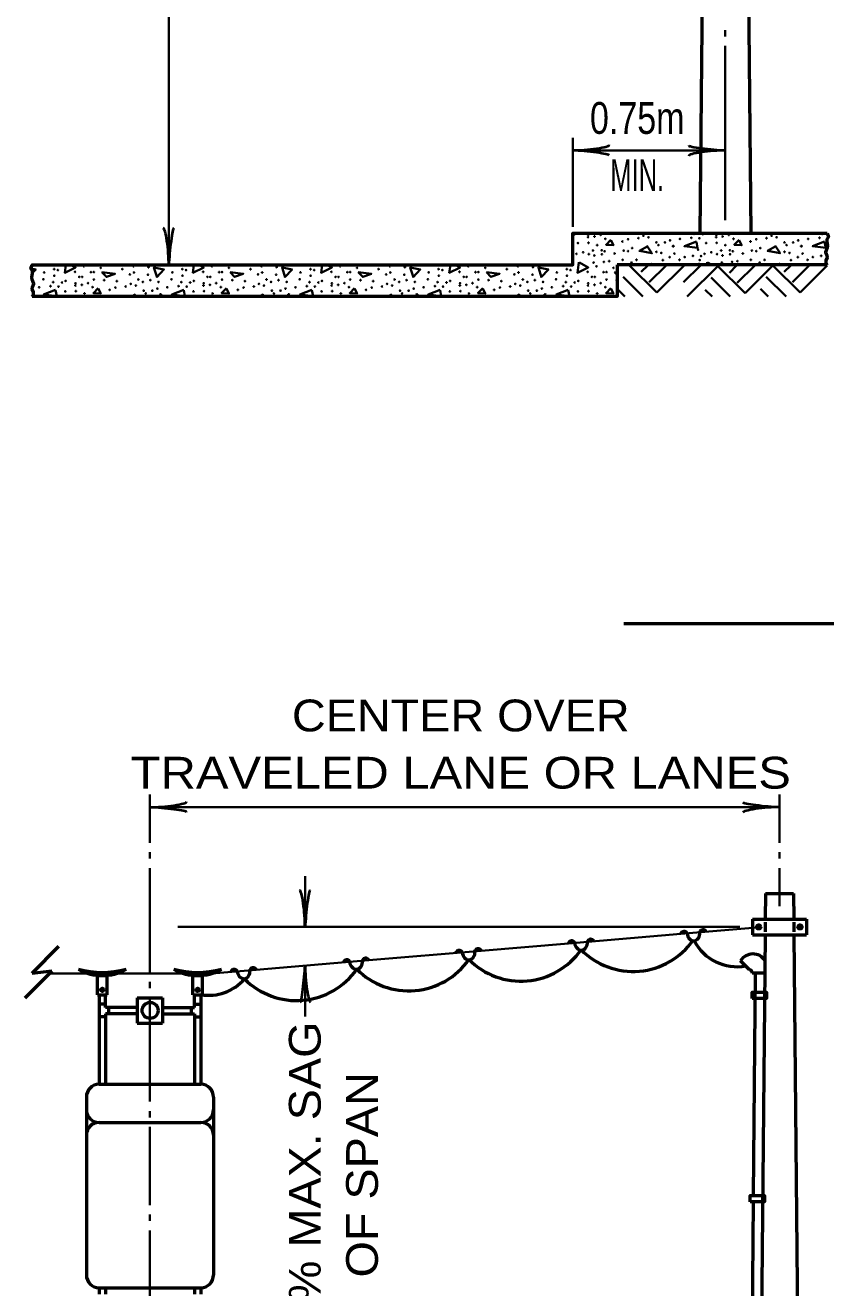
# Model space of a CAD drawing. Extents: x -35 to 821, y -10 to 534.
# Drawn here: x 369.7 to 446, y 205.9 to 325 of the extents above; entities that cross this region are included whole.
import ezdxf
from ezdxf.enums import TextEntityAlignment as Align

# ---------------------------------------------------------------- set-up
doc = ezdxf.new("R2010")
doc.units = 0
doc.header["$LTSCALE"] = 1.2
doc.layers.add('1', color=7, linetype='Continuous', lineweight=35)

msp = doc.modelspace()

# ---------------------------------------------------------------- hatches: boundary and pattern name
at = {"layer": '1'}
for points in [[(439.118, 239.937, 1), (438.73, 239.937, 1)], [(443.008, 239.937, 1), (442.62, 239.937, 1)], [(377.117, 233.997, 1), (376.817, 233.997, 1)], [(386.119, 233.993, 1), (385.819, 233.993, 1)]]:
    msp.add_hatch(color=256, dxfattribs=at).paths.add_polyline_path(points)

# ---------------------------------------------------------------- linework, layer by layer
at = {"layer": '1', "lineweight": 53}
for p, q in [((434.268, 402.619), (433.368, 305.418)), ((437.268, 402.619), (438.168, 305.418)), ((445.368, 302.418), (425.567, 302.418)), ((446.005, 268.555), (426.205, 268.555)), ((439.564, 243.084), (439.542, 240.684)), ((439.564, 243.084), (442.209, 243.084)), ((442.209, 243.084), (442.231, 240.684)), ((438.342, 240.684), (443.431, 240.684)), ((438.342, 240.684), (438.342, 239.184)), ((443.431, 240.684), (443.431, 239.184)), ((439.539, 240.384), (439.531, 239.484)), ((442.234, 240.384), (442.242, 239.484)), ((438.342, 239.184), (443.431, 239.184)), ((439.528, 239.184), (438.487, 126.685)), ((442.245, 239.184), (443.287, 126.685)), ((370.341, 235.562), (372.886, 238.108)), ((438.067, 235.894), (437.219, 236.743)), ((369.701, 233.251), (372.247, 235.797)), ((370.341, 235.562), (372.247, 235.797)), ((376.52, 233.542), (376.52, 235.342)), ((377.42, 233.542), (377.42, 235.342)), ((385.52, 233.542), (385.52, 235.342)), ((386.42, 233.542), (386.42, 235.342)), ((439.495, 235.584), (438.295, 235.584)), ((438.595, 235.584), (438.4, 214.593)), ((376.52, 233.542), (377.42, 233.542)), ((376.67, 233.542), (376.67, 225.085)), ((377.27, 232.342), (377.27, 233.542)), ((385.52, 233.542), (386.42, 233.542)), ((385.67, 232.342), (385.67, 233.542)), ((386.27, 233.542), (386.27, 225.085)), ((377.27, 232.642), (376.67, 232.642)), ((380.27, 232.342), (377.27, 232.342)), ((377.57, 232.342), (377.57, 231.742)), ((380.27, 233.242), (382.67, 233.242)), ((380.27, 233.242), (380.27, 230.842)), ((382.67, 233.242), (382.67, 230.842)), ((382.67, 232.342), (385.67, 232.342)), ((385.37, 232.342), (385.37, 231.742)), ((385.67, 232.642), (386.27, 232.642)), ((377.27, 231.442), (376.67, 231.442)), ((380.27, 231.742), (377.27, 231.742)), ((377.27, 231.742), (377.27, 225.085)), ((382.67, 231.742), (385.67, 231.742)), ((385.67, 231.742), (385.67, 225.085)), ((385.67, 231.442), (386.27, 231.442)), ((380.27, 230.842), (382.67, 230.842)), ((376.67, 225.085), (386.27, 225.085)), ((375.47, 223.885), (375.47, 207.085)), ((387.47, 223.885), (387.47, 207.085)), ((376.67, 221.485), (386.27, 221.485)), ((438.395, 213.985), (437.884, 158.795)), ((376.67, 205.885), (386.27, 205.885)), ((376.67, 205.885), (376.67, 205.285)), ((377.27, 205.885), (377.27, 205.285)), ((385.67, 205.885), (385.67, 205.285)), ((386.27, 205.885), (386.27, 205.285))]:
    msp.add_line(p, q, dxfattribs=at)
at = {"layer": '1'}
for p, q in [((383.251, 393.619), (383.251, 302.418)), ((435.768, 323.979), (435.768, 324.579)), ((435.768, 323.079), (435.768, 306.619)), ((421.368, 306.019), (421.368, 314.418)), ((421.368, 313.219), (435.768, 313.219)), ((434.012, 302.418), (434.049, 302.678)), ((434.097, 302.654), (434.509, 302.418)), ((425.313, 301.718), (425.567, 301.689)), ((425.567, 301.463), (425.313, 301.718)), ((426.744, 302.37), (429.312, 299.803)), ((428.448, 302.37), (427.824, 301.747)), ((430.175, 302.37), (428.591, 300.786)), ((431.88, 302.37), (429.312, 299.803)), ((433.416, 302.37), (431.832, 300.786)), ((435.12, 302.37), (432.168, 299.418)), ((435, 302.37), (437.639, 299.731)), ((436.824, 302.37), (436.151, 301.675)), ((438.552, 302.37), (436.896, 300.714)), ((440.256, 302.37), (437.639, 299.731)), ((440.256, 302.37), (442.824, 299.803)), ((441.96, 302.37), (441.336, 301.747)), ((443.688, 302.37), (442.103, 300.786)), ((445.392, 302.37), (442.824, 299.803)), ((426.12, 301.291), (427.992, 299.418)), ((434.424, 301.219), (436.243, 299.418)), ((439.632, 301.291), (441.504, 299.418)), ((380.073, 299.606), (379.729, 299.418)), ((380.161, 299.418), (380.025, 299.63)), ((392.169, 299.606), (391.825, 299.418)), ((392.257, 299.418), (392.121, 299.63)), ((404.265, 299.606), (403.921, 299.418)), ((404.353, 299.418), (404.217, 299.63)), ((416.361, 299.606), (416.017, 299.418)), ((416.449, 299.418), (416.313, 299.63)), ((425.567, 300.139), (426.288, 299.418)), ((433.872, 300.067), (434.519, 299.418)), ((439.079, 300.139), (439.8, 299.418)), ((381.47, 252.442), (381.47, 247.884)), ((440.887, 247.884), (440.887, 252.442)), ((381.47, 251.242), (440.887, 251.242)), ((381.47, 246.984), (381.47, 246.384)), ((440.887, 246.384), (440.887, 246.984)), ((381.47, 245.484), (381.47, 235.642)), ((440.887, 241.884), (440.887, 245.484)), ((396.113, 239.934), (396.113, 244.734)), ((384.113, 239.934), (437.142, 239.934)), ((431.575, 239.278), (438.738, 239.882)), ((412.739, 237.69), (420.961, 238.384)), ((420.958, 238.383), (431.575, 239.278)), ((402.12, 236.796), (412.739, 237.691)), ((391.505, 235.901), (402.12, 236.796)), ((396.113, 231.489), (396.113, 236.289)), ((375.622, 235.548), (371.998, 235.548)), ((384.622, 235.548), (378.318, 235.548)), ((381.47, 234.742), (381.47, 234.142)), ((387.317, 235.548), (391.505, 235.901)), ((381.47, 229.642), (381.47, 223.464)), ((381.47, 222.564), (381.47, 221.964)), ((381.47, 221.064), (381.47, 214.885)), ((381.47, 214.885), (381.47, 213.685)), ((381.47, 212.785), (381.47, 212.185)), ((381.47, 211.285), (381.47, 197.779))]:
    msp.add_line(p, q, dxfattribs=at)
at = {"layer": '1', "lineweight": 53}
for points in [[(370.368, 299.418), (370.477, 299.576), (370.483, 299.832), (370.352, 300.126), (370.372, 300.296), (370.509, 300.623), (370.359, 301.036), (370.326, 301.225), (370.392, 301.631), (370.372, 301.821), (370.235, 302.076), (370.368, 302.418), (421.368, 302.418), (421.368, 305.418), (445.368, 305.418)], [(445.368, 305.418), (445.501, 305.076), (445.363, 304.821), (445.344, 304.631), (445.409, 304.225), (445.376, 304.036), (445.226, 303.623), (445.363, 303.296), (445.383, 303.126), (445.252, 302.832), (445.258, 302.576), (445.368, 302.418)], [(425.567, 302.418), (425.567, 299.418), (370.368, 299.418)]]:
    msp.add_lwpolyline(points, dxfattribs=at)
at = {"layer": '1'}
for points in [[(424.977, 304.79), (424.521, 304.31), (425.217, 304.262), (424.977, 304.742)], [(428.457, 304.166), (427.665, 303.734), (428.841, 303.518), (428.409, 304.19)], [(433.041, 304.622), (431.913, 304.166), (433.161, 304.022), (433.041, 304.574)], [(437.073, 304.79), (436.617, 304.31), (437.313, 304.262), (437.073, 304.742)], [(440.553, 304.166), (439.761, 303.734), (440.937, 303.518), (440.505, 304.19)], [(445.137, 304.622), (444.009, 304.166), (445.257, 304.022), (445.137, 304.574)], [(422.001, 302.654), (422.841, 302.174), (421.809, 301.67), (421.953, 302.678)], [(370.235, 302.075), (370.689, 301.982), (370.389, 301.66)], [(374.029, 302.418), (374.457, 302.174), (373.425, 301.67), (373.531, 302.418)], [(382.137, 301.214), (381.849, 302.174), (382.785, 301.982), (382.113, 301.262)], [(386.125, 302.418), (386.553, 302.174), (385.521, 301.67), (385.627, 302.418)], [(394.233, 301.214), (393.945, 302.174), (394.881, 301.982), (394.209, 301.262)], [(398.221, 302.418), (398.649, 302.174), (397.617, 301.67), (397.724, 302.418)], [(406.329, 301.214), (406.041, 302.174), (406.977, 301.982), (406.305, 301.262)], [(410.317, 302.418), (410.745, 302.174), (409.713, 301.67), (409.82, 302.418)], [(418.425, 301.214), (418.137, 302.174), (419.073, 301.982), (418.401, 301.262)], [(372.561, 300.062), (371.433, 299.606), (372.681, 299.462), (372.561, 300.014)], [(376.593, 300.23), (376.137, 299.75), (376.833, 299.702), (376.593, 300.182)], [(384.657, 300.062), (383.529, 299.606), (384.777, 299.462), (384.657, 300.014)], [(388.689, 300.23), (388.233, 299.75), (388.929, 299.702), (388.689, 300.182)], [(396.753, 300.062), (395.625, 299.606), (396.873, 299.462), (396.753, 300.014)], [(400.785, 300.23), (400.329, 299.75), (401.025, 299.702), (400.785, 300.182)], [(408.849, 300.062), (407.721, 299.606), (408.969, 299.462), (408.849, 300.014)], [(412.881, 300.23), (412.425, 299.75), (413.121, 299.702), (412.881, 300.182)], [(420.945, 300.062), (419.817, 299.606), (421.065, 299.462), (420.945, 300.014)], [(424.977, 300.23), (424.521, 299.75), (425.217, 299.702), (424.977, 300.182)], [(381.47, 233.242), (381.47, 230.242), (381.47, 229.642)]]:
    msp.add_lwpolyline(points, dxfattribs=at)
for points in [[(376.929, 301.718), (378.177, 301.574), (377.361, 301.286)], [(389.025, 301.718), (390.273, 301.574), (389.457, 301.286)], [(401.121, 301.718), (402.369, 301.574), (401.553, 301.286)], [(413.217, 301.718), (414.465, 301.574), (413.649, 301.286)]]:
    msp.add_lwpolyline(points, close=True, dxfattribs=at)
at = {"layer": '1', "lineweight": 53}
for points in [[(438.295, 233.184), (438.295, 233.784), (439.645, 233.784), (439.645, 233.184)], [(438.123, 213.993), (438.123, 214.593), (439.473, 214.593), (439.473, 213.993)]]:
    msp.add_lwpolyline(points, close=True, dxfattribs=at)
at = {"layer": '1'}
for centre in [(421.56, 305.314), (422.816, 305.034), (422.832, 305.235), (423.42, 305.097), (424.009, 305.251), (428.042, 305.171), (428.519, 305.018), (429.187, 305.362), (430.666, 305.362), (432.813, 305.346), (433.656, 305.314), (434.912, 305.034), (434.928, 305.235), (435.516, 305.097), (436.105, 305.251), (440.138, 305.171), (440.615, 305.018), (441.283, 305.362), (442.762, 305.362), (444.909, 305.346), (421.862, 304.477), (422.864, 304.493), (423.675, 304.27), (424.104, 303.793), (424.447, 304.875), (426.054, 304.62), (426.594, 304.827), (426.976, 304), (427.564, 304.938), (429.266, 304.541), (429.457, 304.286), (430.077, 304.541), (430.554, 304.731), (430.825, 304.175), (430.888, 304.175), (431.493, 304.859), (432.558, 304.97), (433.194, 303.856), (433.322, 304.922), (433.958, 304.477), (434.96, 304.493), (435.771, 304.27), (436.2, 303.793), (436.543, 304.875), (438.15, 304.62), (438.69, 304.827), (439.072, 304), (439.66, 304.938), (441.362, 304.541), (441.553, 304.286), (442.173, 304.541), (442.65, 304.731), (442.921, 304.175), (442.984, 304.175), (443.589, 304.859), (444.654, 304.97), (421.719, 303.459), (422.355, 303.602), (422.896, 303.427), (423.277, 303.777), (423.341, 302.631), (423.404, 303.3), (424.12, 303.411), (424.311, 302.695), (424.384, 303.697), (424.813, 302.759), (425.322, 303.49), (426.085, 302.886), (426.181, 303.761), (426.594, 303.713), (426.912, 302.631), (427.389, 302.886), (429.266, 303.65), (429.727, 303.538), (429.87, 302.854), (430.523, 303.141), (430.968, 303.475), (431.445, 302.886), (431.938, 303.156), (432.717, 303.268), (433.353, 302.87), (433.481, 303.252), (433.815, 303.459), (434.451, 303.602), (434.992, 303.427), (435.373, 303.777), (435.437, 302.631), (435.5, 303.3), (436.216, 303.411), (436.407, 302.695), (436.48, 303.697), (436.909, 302.759), (437.418, 303.49), (438.181, 302.886), (438.277, 303.761), (438.69, 303.713), (439.008, 302.631), (439.485, 302.886), (441.362, 303.65), (441.823, 303.538), (441.966, 302.854), (442.619, 303.141), (443.064, 303.475), (443.541, 302.886), (444.034, 303.156), (444.813, 303.268), (371.49, 301.709), (372.428, 302.011), (372.778, 301.931), (374.4, 301.756), (375.227, 302.281), (375.903, 301.722), (376.175, 301.741), (376.827, 302.138), (378.862, 302.011), (379.578, 301.518), (379.912, 302.281), (379.96, 301.693), (381.28, 301.486), (381.327, 302.202), (383.586, 301.709), (384.524, 302.011), (384.874, 301.931), (386.496, 301.756), (387.323, 302.281), (387.999, 301.722), (388.271, 301.741), (388.923, 302.138), (390.958, 302.011), (391.674, 301.518), (392.008, 302.281), (392.056, 301.693), (393.376, 301.486), (393.423, 302.202), (395.682, 301.709), (396.62, 302.011), (396.97, 301.931), (398.592, 301.756), (399.419, 302.281), (400.095, 301.722), (400.367, 301.741), (401.019, 302.138), (403.054, 302.011), (403.77, 301.518), (404.104, 302.281), (404.152, 301.693), (405.472, 301.486), (405.519, 302.202), (407.778, 301.709), (408.716, 302.011), (409.066, 301.931), (410.688, 301.756), (411.515, 302.281), (412.191, 301.722), (412.463, 301.741), (413.115, 302.138), (415.15, 302.011), (415.866, 301.518), (416.2, 302.281), (416.248, 301.693), (417.568, 301.486), (417.615, 302.202), (419.874, 301.709), (420.812, 302.011), (421.162, 301.931), (422.784, 301.756), (423.611, 302.281), (424.287, 301.722), (424.559, 301.741), (425.211, 302.138), (428.789, 302.488), (433.274, 302.504), (440.885, 302.488), (371.013, 300.299), (371.41, 301.056), (372.078, 300.41), (372.333, 300.786), (372.444, 301.391), (372.842, 300.362), (373.176, 300.754), (373.51, 300.897), (374.432, 300.474), (374.448, 300.675), (374.798, 301.279), (375.036, 300.537), (375.068, 301.279), (375.625, 300.691), (376.063, 300.315), (376.175, 301.025), (377.145, 300.977), (378.21, 300.267), (378.338, 300.881), (379.18, 300.378), (379.658, 300.611), (380.135, 300.458), (380.373, 301.041), (380.803, 300.802), (381.502, 300.977), (382.282, 300.802), (383.109, 300.299), (383.506, 301.056), (384.174, 300.41), (384.429, 300.786), (384.54, 301.391), (384.938, 300.362), (385.272, 300.754), (385.606, 300.897), (386.528, 300.474), (386.544, 300.675), (386.894, 301.279), (387.132, 300.537), (387.164, 301.279), (387.721, 300.691), (388.159, 300.315), (388.271, 301.025), (389.241, 300.977), (390.306, 300.267), (390.434, 300.881), (391.276, 300.378), (391.754, 300.611), (392.231, 300.458), (392.469, 301.041), (392.899, 300.802), (393.598, 300.977), (394.378, 300.802), (395.205, 300.299), (395.602, 301.056), (396.27, 300.41), (396.525, 300.786), (396.636, 301.391), (397.034, 300.362), (397.368, 300.754), (397.702, 300.897), (398.624, 300.474), (398.64, 300.675), (398.99, 301.279), (399.228, 300.537), (399.26, 301.279), (399.817, 300.691), (400.255, 300.315), (400.367, 301.025), (401.337, 300.977), (402.402, 300.267), (402.53, 300.881), (403.372, 300.378), (403.85, 300.611), (404.327, 300.458), (404.565, 301.041), (404.995, 300.802), (405.694, 300.977), (406.474, 300.802), (407.301, 300.299), (407.698, 301.056), (408.366, 300.41), (408.621, 300.786), (408.732, 301.391), (409.13, 300.362), (409.464, 300.754), (409.798, 300.897), (410.72, 300.474), (410.736, 300.675), (411.086, 301.279), (411.324, 300.537), (411.356, 301.279), (411.913, 300.691), (412.351, 300.315), (412.463, 301.025), (413.433, 300.977), (414.498, 300.267), (414.626, 300.881), (415.468, 300.378), (415.946, 300.611), (416.423, 300.458), (416.661, 301.041), (417.091, 300.802), (417.79, 300.977), (418.57, 300.802), (419.397, 300.299), (419.794, 301.056), (420.462, 300.41), (420.717, 300.786), (420.828, 301.391), (421.226, 300.362), (421.56, 300.754), (421.894, 300.897), (422.816, 300.474), (422.832, 300.675), (423.182, 301.279), (423.42, 300.537), (423.452, 301.279), (424.009, 300.691), (424.447, 300.315), (424.559, 301.025), (425.529, 300.977), (373.478, 299.917), (374.48, 299.933), (375.291, 299.71), (377.67, 300.06), (380.882, 299.981), (381.073, 299.726), (381.693, 299.981), (382.17, 300.171), (382.441, 299.615), (382.504, 299.615), (385.574, 299.917), (386.576, 299.933), (387.387, 299.71), (389.766, 300.06), (392.978, 299.981), (393.169, 299.726), (393.789, 299.981), (394.266, 300.171), (394.537, 299.615), (394.6, 299.615), (397.67, 299.917), (398.672, 299.933), (399.483, 299.71), (401.862, 300.06), (405.074, 299.981), (405.265, 299.726), (405.885, 299.981), (406.362, 300.171), (406.633, 299.615), (406.696, 299.615), (409.766, 299.917), (410.768, 299.933), (411.579, 299.71), (413.958, 300.06), (417.17, 299.981), (417.361, 299.726), (417.981, 299.981), (418.458, 300.171), (418.729, 299.615), (418.792, 299.615), (421.862, 299.917), (422.864, 299.933), (423.675, 299.71)]:
    msp.add_circle(centre, 0.0318, dxfattribs=at)
at = {"layer": '1', "lineweight": 53}
for centre, radius in [((438.924, 239.937), 0.194), ((442.814, 239.937), 0.194), ((376.967, 233.997), 0.15), ((385.969, 233.993), 0.15), ((381.484, 232.055), 0.75)]:
    msp.add_circle(centre, radius, dxfattribs=at)
at = {"layer": '1'}
for centre, start, end in [((426.722, 305.441), 226.35082, 313.64918), ((438.818, 305.441), 226.35082, 313.64918), ((445.29, 303.856), 32.83014, 287.06312), ((445.418, 304.922), 61.61934, 241.7845), ((421.385, 303.252), 237.37076, 122.62924), ((371.299, 302.441), 223.9797, 316.0203), ((371.919, 302.409), 162.01481, 17.98519), ((377.638, 302.409), 162.01481, 17.98519), ((383.395, 302.441), 223.9797, 316.0203), ((384.015, 302.409), 162.01481, 17.98519), ((389.734, 302.409), 162.01481, 17.98519), ((395.491, 302.441), 223.9797, 316.0203), ((396.111, 302.409), 162.01481, 17.98519), ((401.83, 302.409), 162.01481, 17.98519), ((407.587, 302.441), 223.9797, 316.0203), ((408.207, 302.409), 162.01481, 17.98519), ((413.926, 302.409), 162.01481, 17.98519), ((419.683, 302.441), 223.9797, 316.0203), ((420.303, 302.409), 162.01481, 17.98519), ((426.022, 302.409), 17.98519, 162.01481), ((431.779, 302.441), 316.0203, 223.9797), ((432.399, 302.409), 17.98519, 162.01481), ((438.118, 302.409), 17.98519, 162.01481), ((443.875, 302.441), 316.0203, 223.9797), ((444.495, 302.409), 17.98519, 162.01481), ((378.592, 299.44), 318.30023, 221.69977), ((390.688, 299.44), 318.30023, 221.69977), ((402.784, 299.44), 318.30023, 221.69977), ((414.88, 299.44), 318.30023, 221.69977)]:
    msp.add_arc(centre, 0.0318, start, end, dxfattribs=at)
at = {"layer": '1', "lineweight": 53}
for centre, radius, start, end in [((431.883, 239.192), 0.32, 25.5313, 164.45861), ((433.676, 239.349), 0.32, 24.08975, 164.4687), ((421.267, 238.297), 0.32, 25.5313, 164.45861), ((427.062, 242.653), 6.917, 224.78783, 325.11132), ((423.06, 238.454), 0.32, 24.08975, 164.4687), ((436.868, 240.732), 4.547, 207.50003, 280.53329), ((410.653, 237.403), 0.32, 25.5313, 164.45861), ((416.479, 241.736), 6.917, 224.78783, 325.11132), ((412.446, 237.56), 0.32, 24.08975, 164.4687), ((438.374, 236.03), 1.357, 32.91213, 148.34152), ((376.97, 244.23), 8.588, 254.81071, 285.18929), ((376.97, 239.861), 4.519, 240.13717, 299.86284), ((385.97, 244.23), 8.588, 254.81071, 285.18929), ((385.97, 239.861), 4.519, 240.13717, 299.86284), ((389.42, 235.613), 0.32, 25.5313, 164.45861), ((395.314, 239.903), 6.917, 224.78783, 325.11132), ((391.213, 235.77), 0.32, 24.08975, 164.4687), ((400.035, 236.508), 0.32, 25.5313, 164.45861), ((405.897, 240.82), 6.917, 224.78783, 325.11132), ((401.828, 236.665), 0.32, 24.08975, 164.4687), ((387.002, 237.997), 4.514, 260.66909, 318.91993), ((438.057, 235.648), 0.246, 344.97633, 87.57779), ((376.67, 223.885), 1.2, 90, 180), ((386.27, 223.885), 1.2, 0, 90), ((376.67, 222.685), 1.2, 180, 270), ((386.27, 222.685), 1.2, 270, 0), ((376.67, 220.285), 1.2, 90, 180), ((386.27, 220.285), 1.2, 0, 90), ((376.67, 207.085), 1.2, 180, 270), ((386.27, 207.085), 1.2, 270, 0)]:
    msp.add_arc(centre, radius, start, end, dxfattribs=at)
at = {"layer": '1', "lineweight": 40}
for centre, major_axis, ratio, start_param, end_param in [((422.677, 313.55), (-2.143, -0.187), 0.122415, 0.8963533, 3.1415927), ((422.677, 313.55), (-2.143, -0.187), 0.122415, 0.8963533, 3.1415927), ((434.423, 313.472), (2.108, -0.211), 0.07063, 3.1407148, 5.41811), ((422.712, 312.965), (-2.108, 0.211), 0.07063, 3.1407148, 5.41811), ((422.712, 312.965), (-2.108, 0.211), 0.07063, 3.1407148, 5.41811), ((434.458, 312.887), (2.143, 0.187), 0.122415, 0.8963533, 3.1415927), ((382.919, 303.728), (0.187, -2.143), 0.122415, 0.8963533, 3.1415927), ((383.505, 303.763), (-0.211, -2.108), 0.07063, 3.1407148, 5.41811), ((382.79, 251.564), (-2.143, -0.187), 0.122415, 0.8963533, 3.1415927), ((439.542, 251.496), (2.108, -0.211), 0.07063, 3.1407148, 5.41811), ((382.825, 250.979), (-2.108, 0.211), 0.07063, 3.1407148, 5.41811), ((439.577, 250.911), (2.143, 0.187), 0.122415, 0.8963533, 3.1415927), ((395.782, 241.243), (0.187, -2.143), 0.122415, 0.8963533, 3.1415927), ((395.782, 241.243), (0.187, -2.143), 0.122415, 0.8963533, 3.1415927), ((396.367, 241.278), (-0.211, -2.108), 0.07063, 3.1407148, 5.41811), ((396.367, 241.278), (-0.211, -2.108), 0.07063, 3.1407148, 5.41811), ((395.859, 234.945), (0.211, 2.108), 0.07063, 3.1407148, 5.41811), ((395.859, 234.945), (0.211, 2.108), 0.07063, 3.1407148, 5.41811), ((396.445, 234.98), (-0.187, 2.143), 0.122415, 0.8963533, 3.1415927), ((396.445, 234.98), (-0.187, 2.143), 0.122415, 0.8963533, 3.1415927)]:
    msp.add_ellipse(centre, major_axis=major_axis, ratio=ratio, start_param=start_param, end_param=end_param, dxfattribs=at)
at = {"layer": '1', "lineweight": 53}
for centre in [(422.153, 238.488), (432.77, 239.383), (411.54, 237.593), (400.922, 236.698), (390.306, 235.804)]:
    msp.add_ellipse(centre, major_axis=(0.066, -0.751), ratio=0.795507, start_param=4.712389, end_param=7.8539816, dxfattribs=at)

# ---------------------------------------------------------------- texts
at = {"layer": '1'}
for s, width, p in [('0.75m', 0.8, (427.458, 314.779)), ('MIN.', 0.6, (427.458, 309.379)), ('CENTER OVER', 1.1, (410.807, 258.39)), ('TRAVELED LANE OR LANES', 1.15, (410.807, 252.99))]:
    msp.add_text(s, height=3, dxfattribs=dict(at, width=width)).set_placement(p, align=Align.CENTER)
at = {"layer": '1', "width": 1.1}
for s, p in [('5% MAX. SAG', (397.584, 216.54)), ('OF SPAN', (402.984, 216.54))]:
    msp.add_text(s, height=3, rotation=90, dxfattribs=at).set_placement(p, align=Align.CENTER)

doc.saveas('drawing.dxf')
